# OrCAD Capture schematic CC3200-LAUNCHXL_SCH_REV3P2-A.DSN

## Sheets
1 5. Sensors. Power: size A2; title: CC3101 LP Ver 2.0; rev: A; company: Texas Instruments; note: 66/3 Bagmane Tech Park; note: CV Raman Nagar
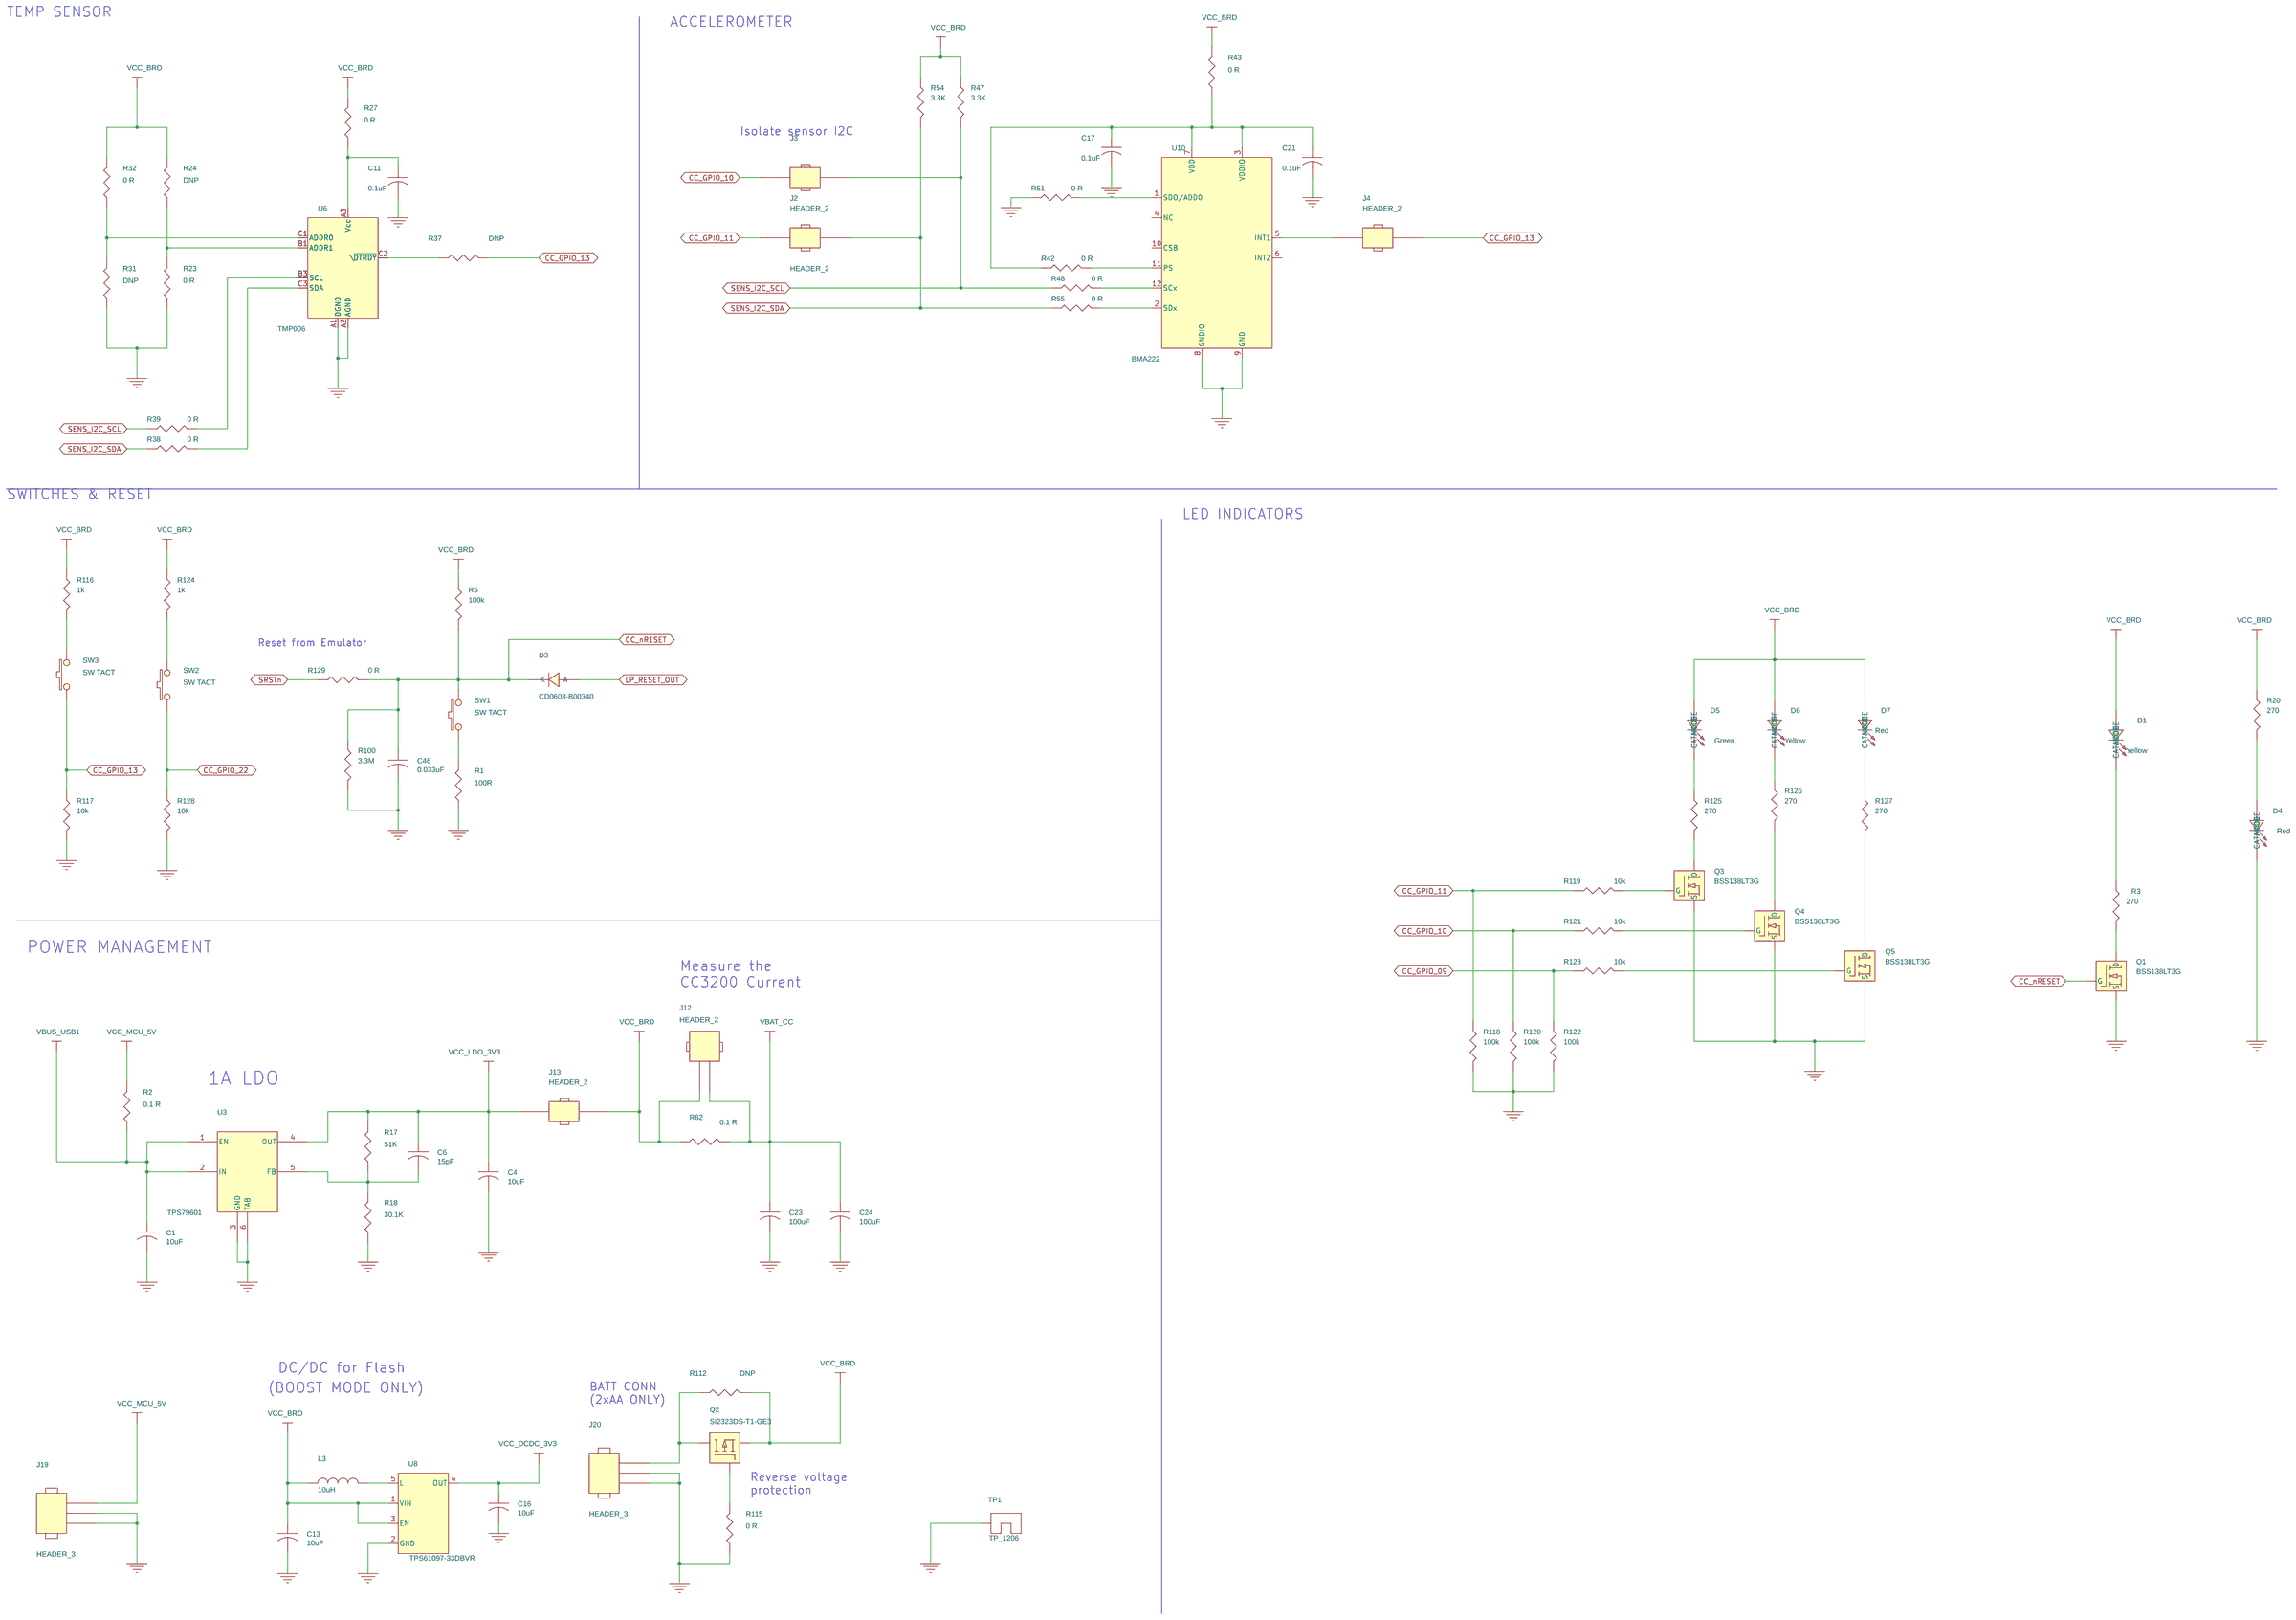
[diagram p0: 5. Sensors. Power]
2 4. ICDI: size A2; title: CC3101 LP Ver 3.0
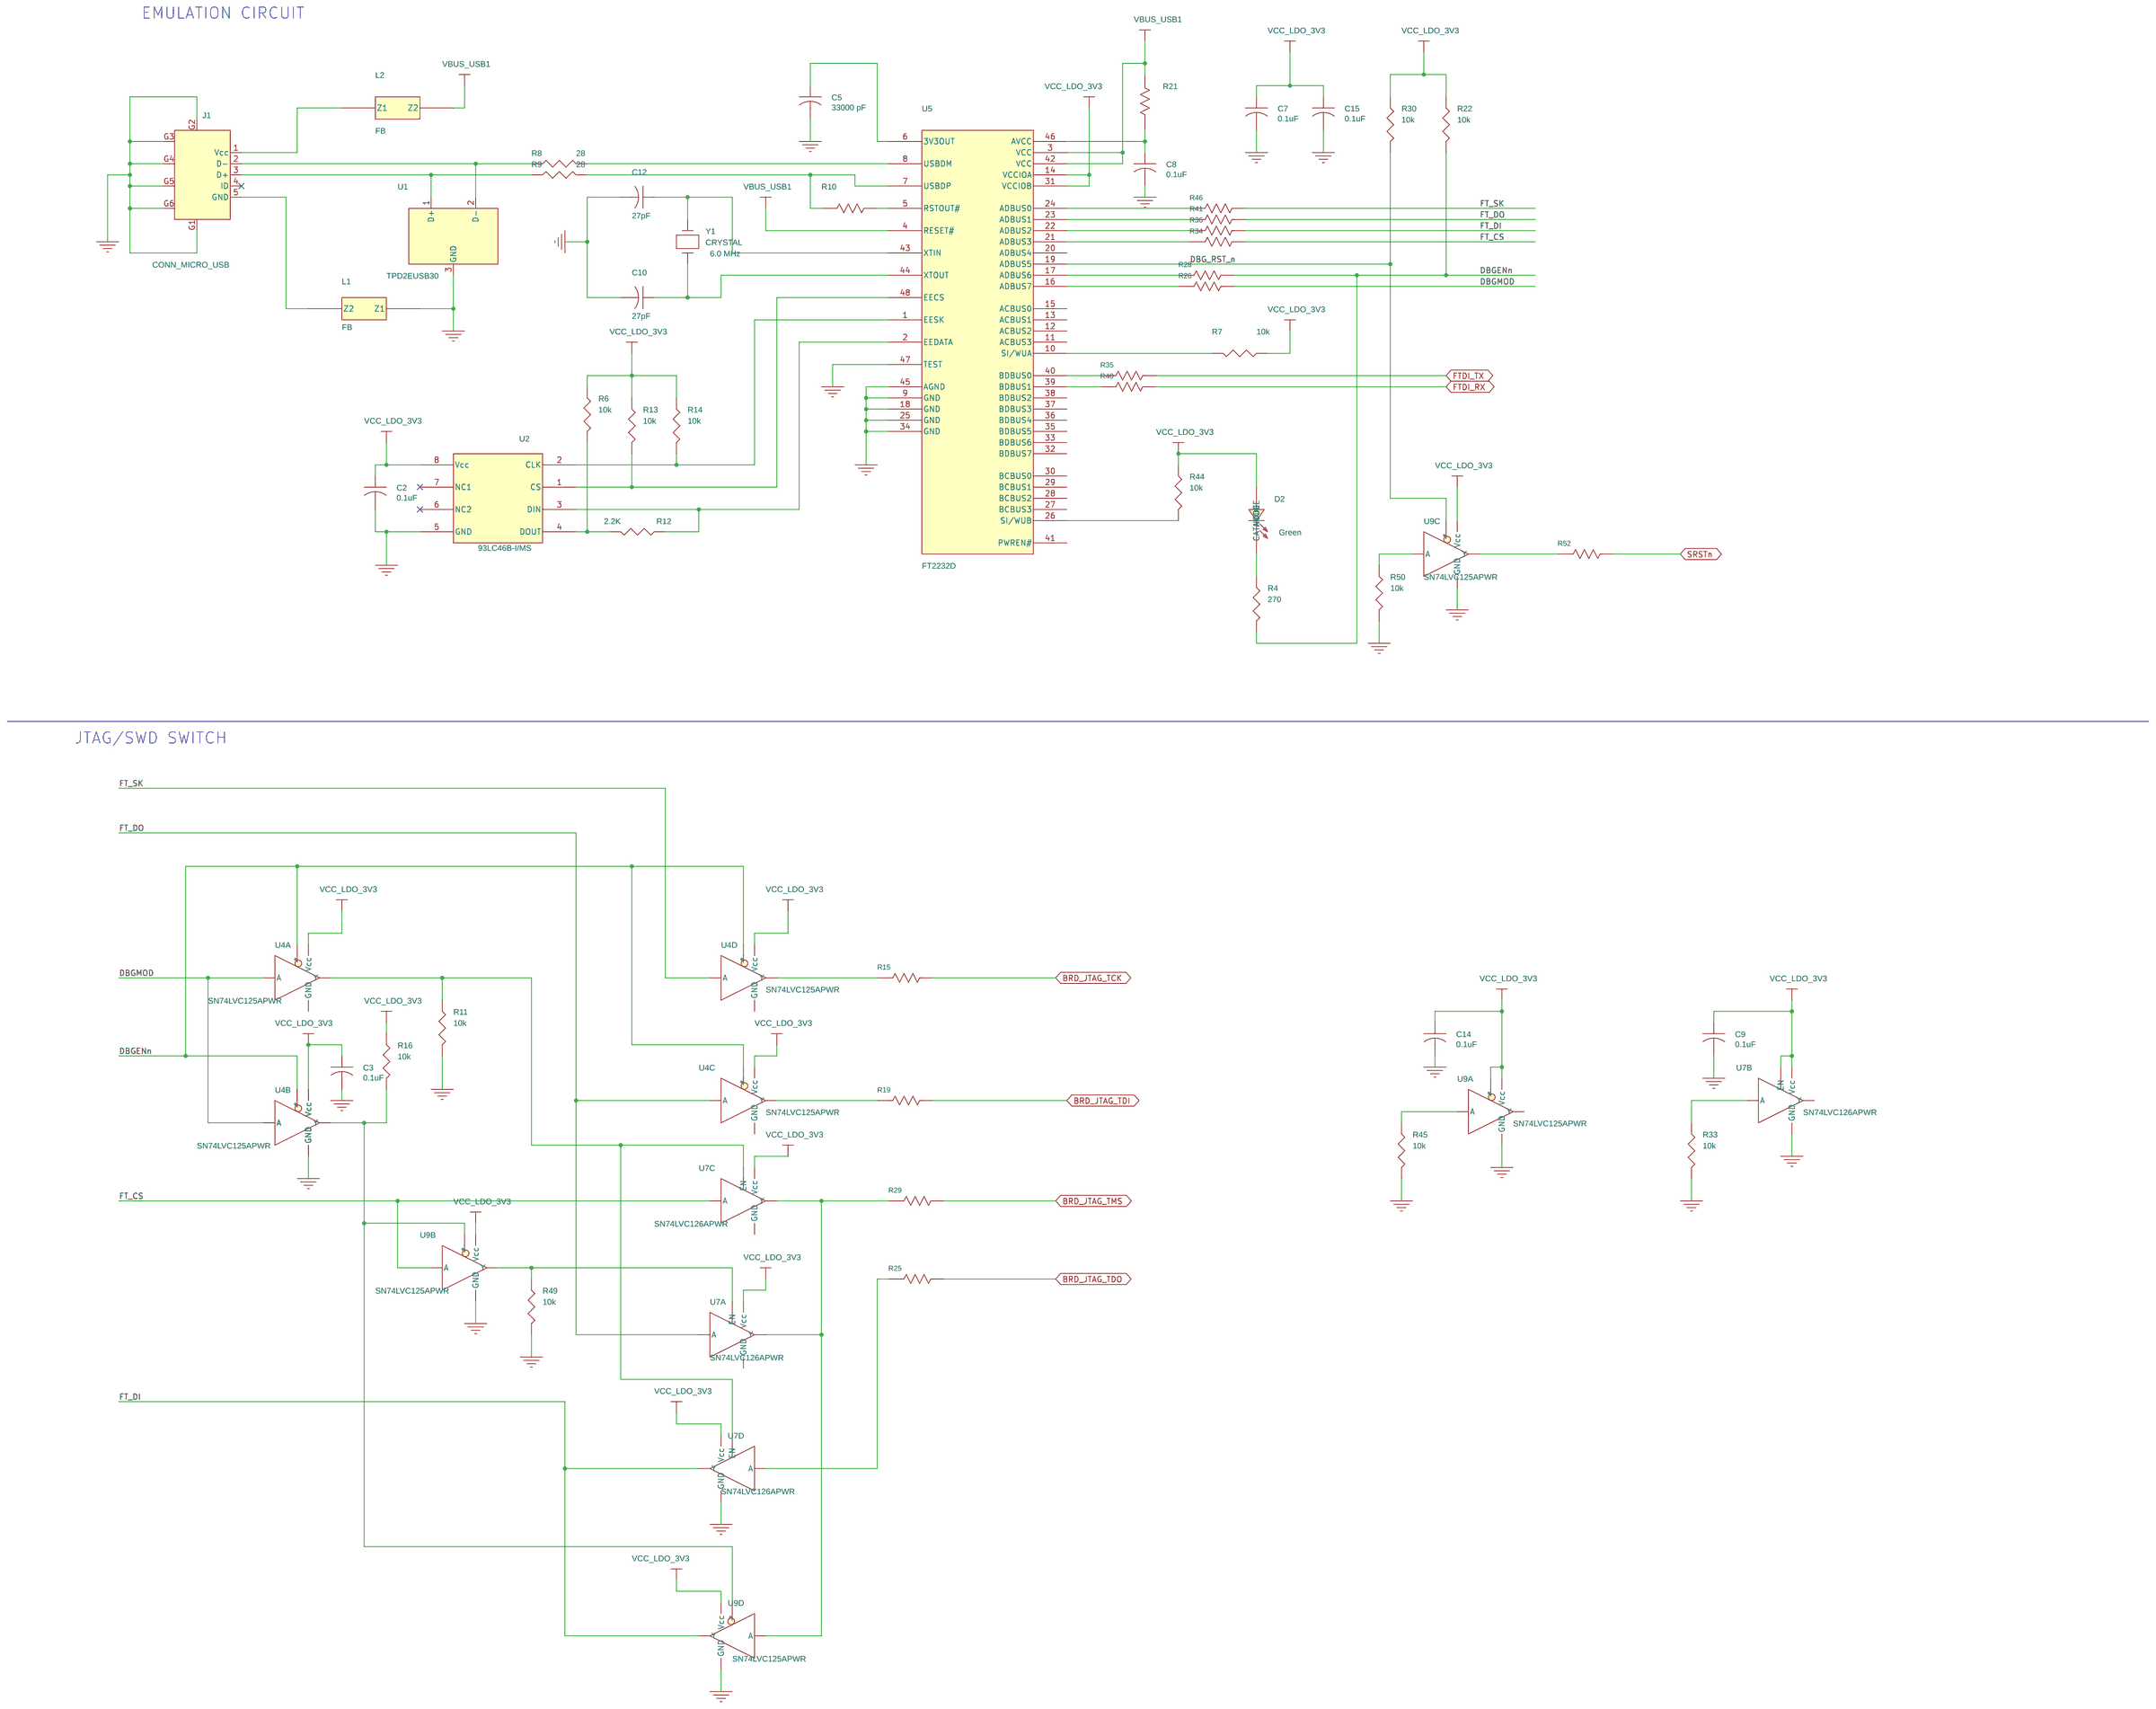
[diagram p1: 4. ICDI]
3 3. HOST INTERFACE: size A2
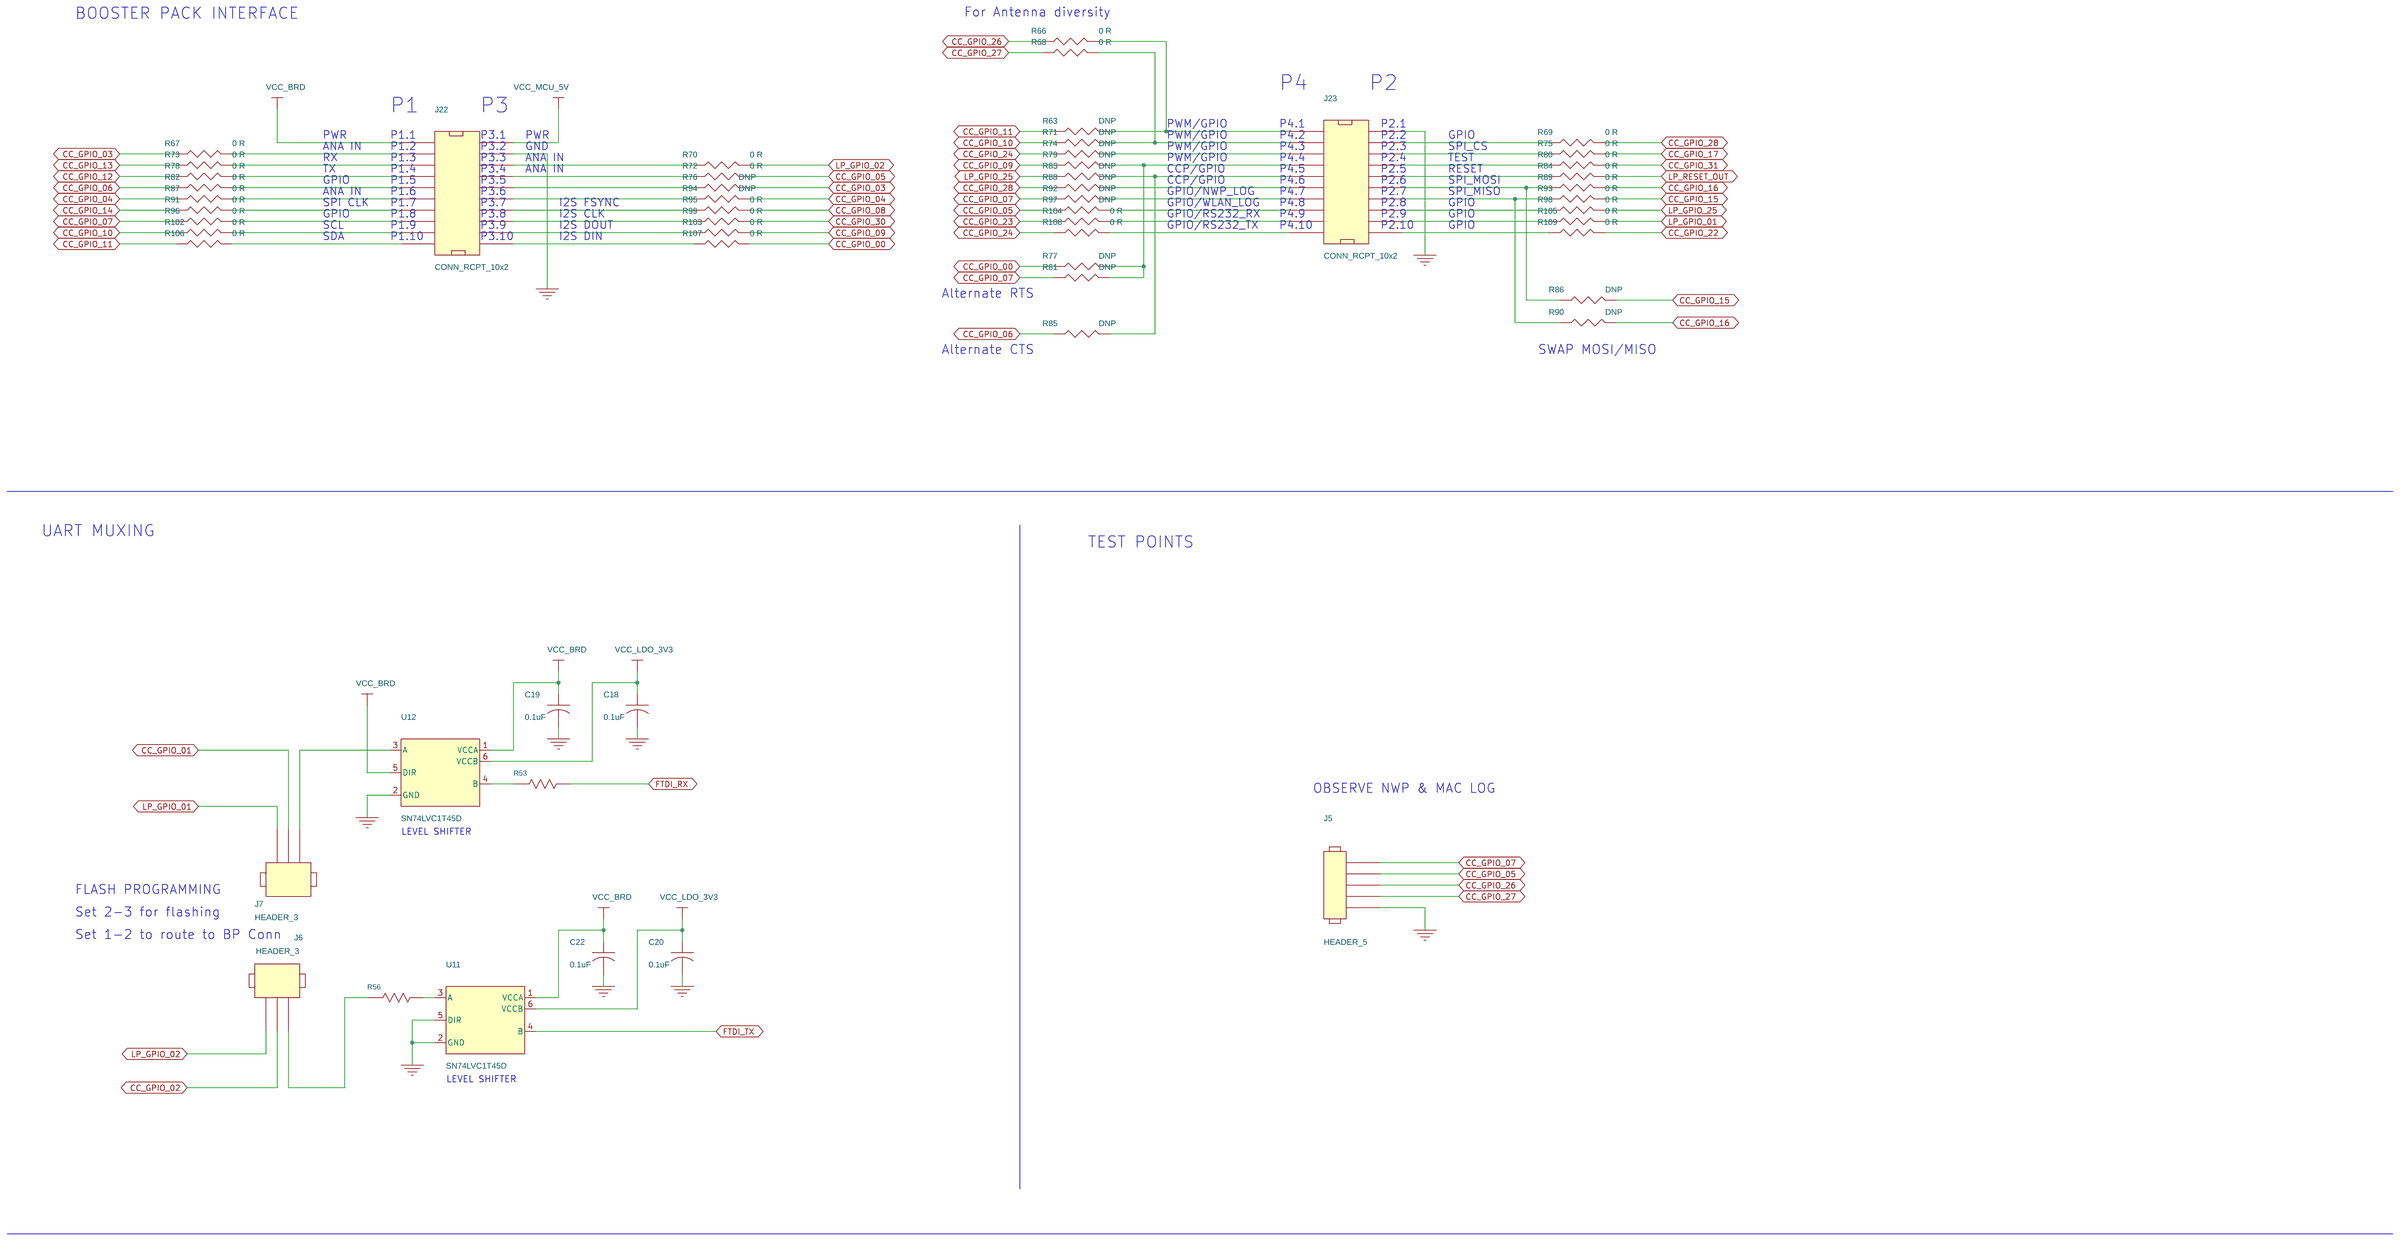
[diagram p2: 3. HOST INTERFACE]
4 2. Main Page: size A2; title: CC3101 LP Ver 3.0; rev: B
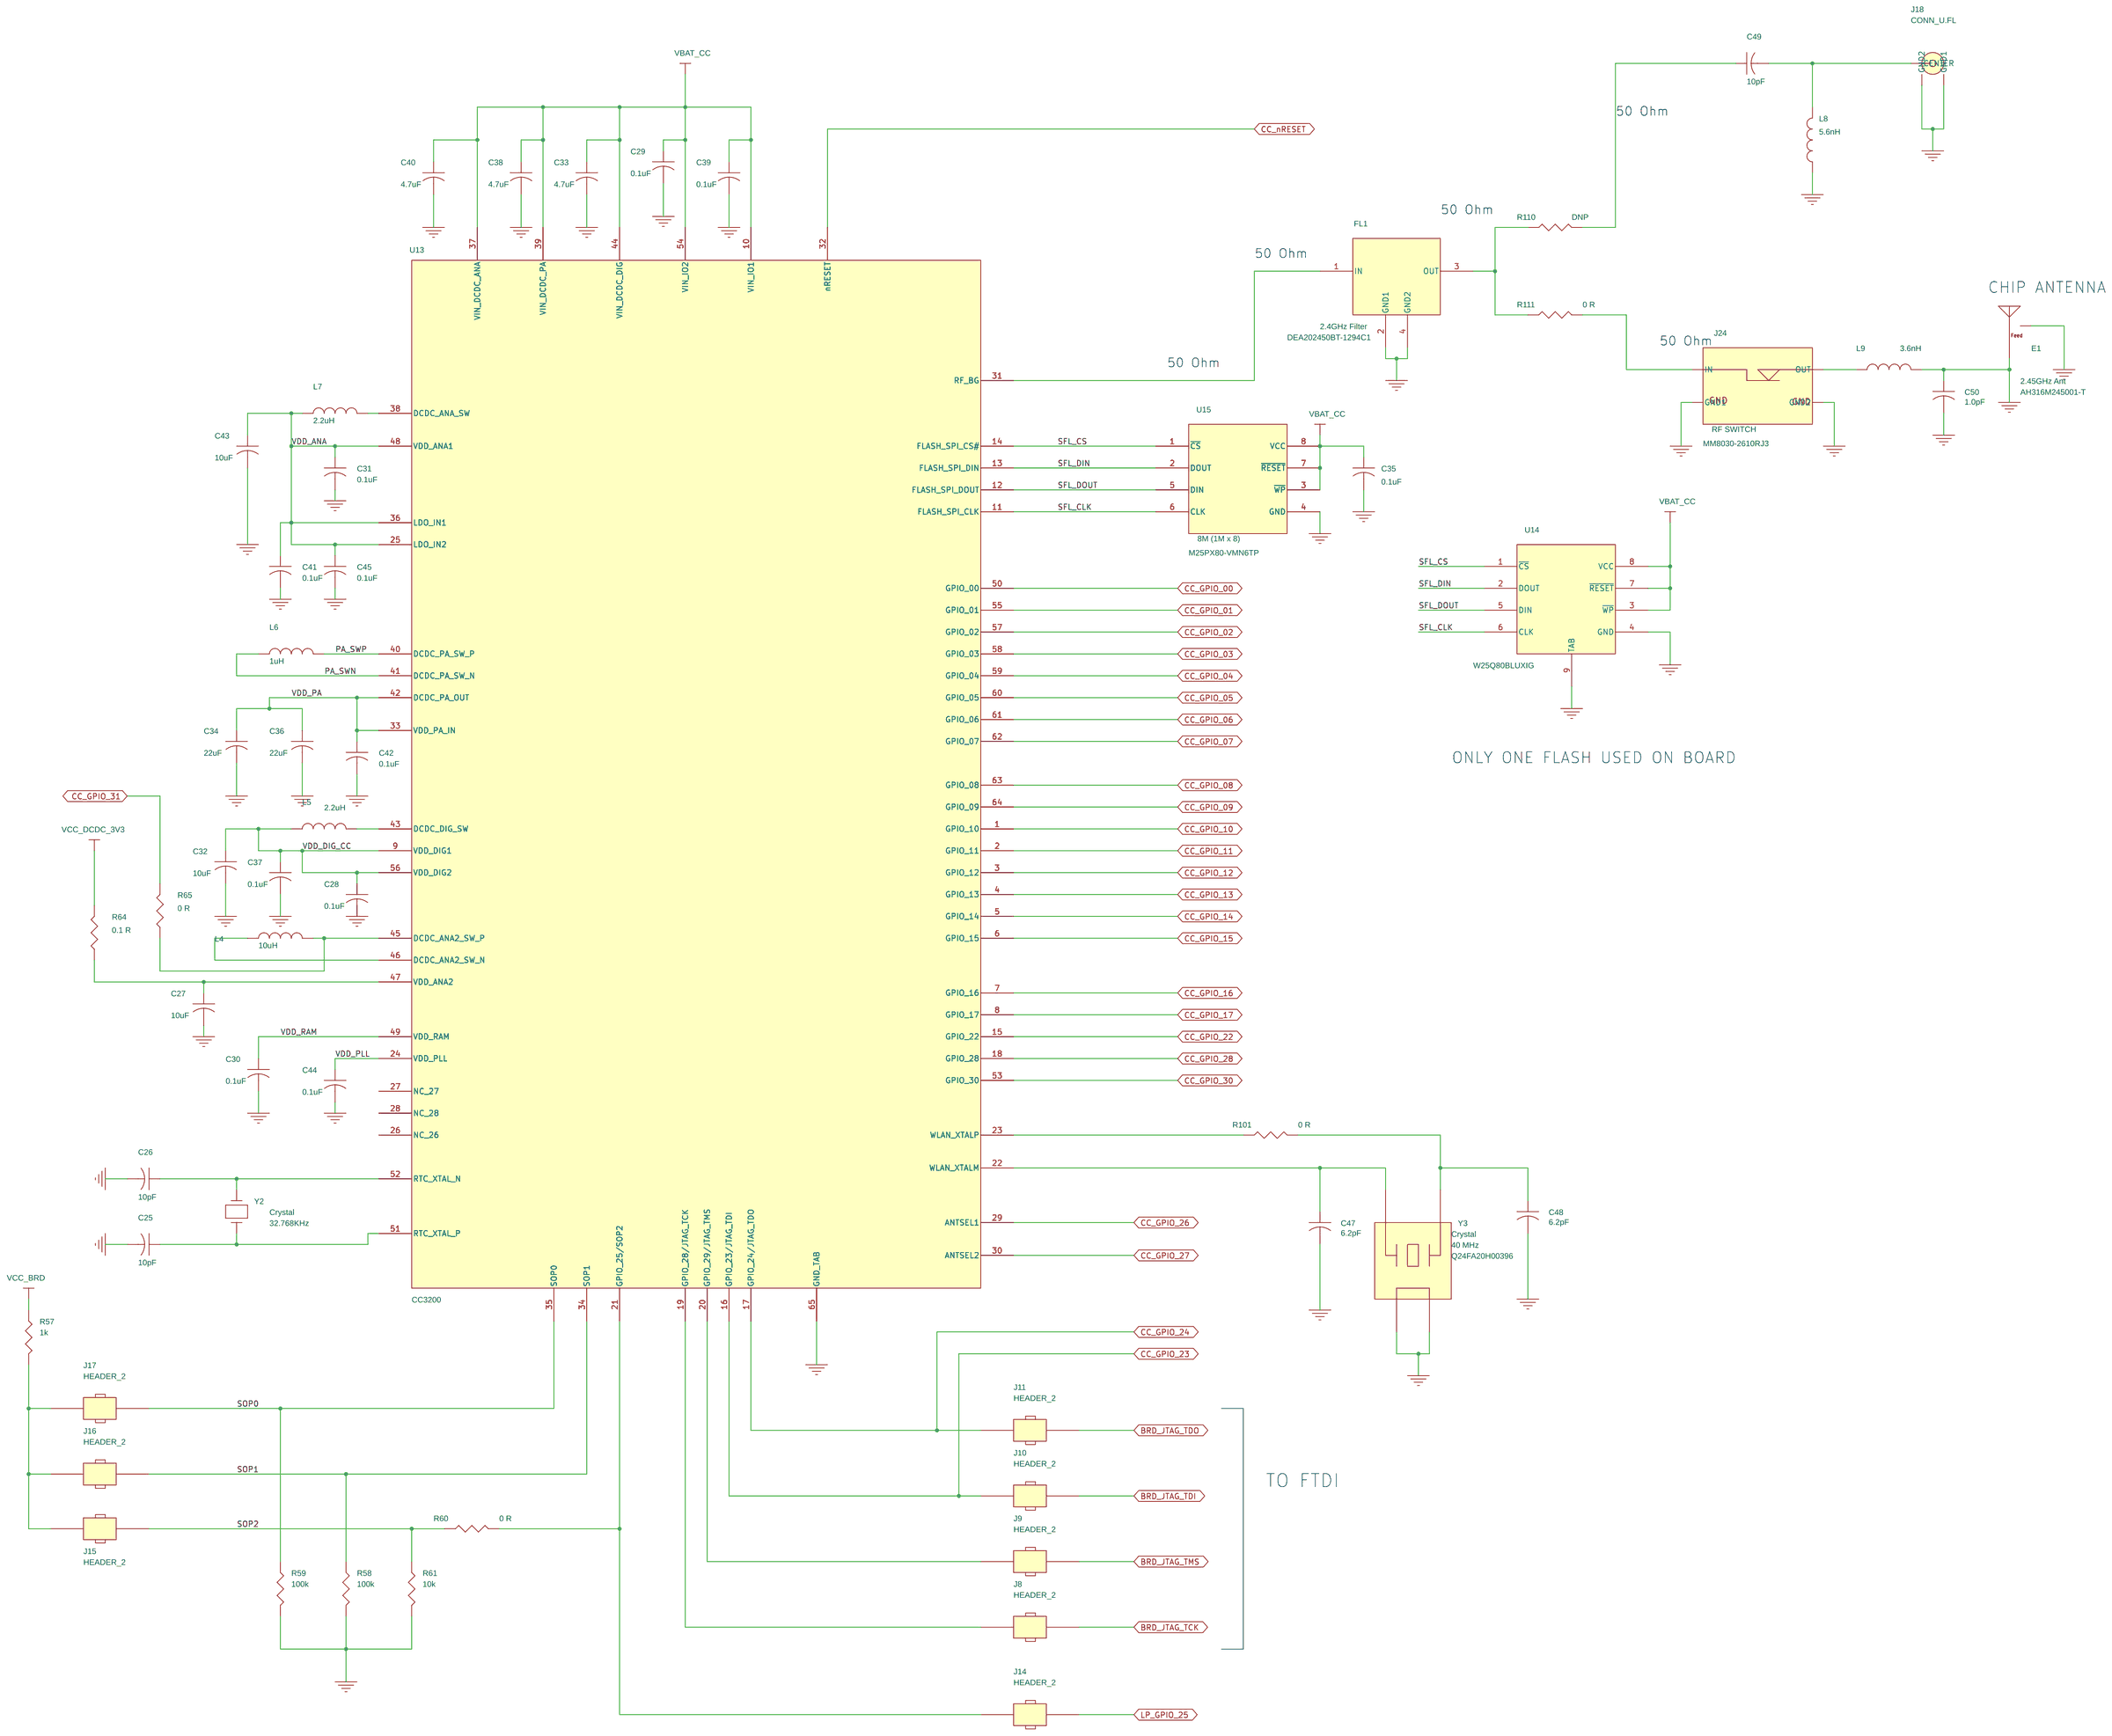
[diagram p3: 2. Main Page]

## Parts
sheet 2. Main Page
C25  10pF  [CC0402]
C26  10pF  [CC0402]
C27  10uF  [CC0603]
C28  0.1uF  [CC0402]
C29  0.1uF  [CC0402]
C30  0.1uF  [CC0402]
C31  0.1uF  [CC0402]
C32  10uF  [CC0603]
C33  4.7uF  [CC0402]
C34  22uF  [CC0603]
C35  0.1uF  [CC0402]
C36  22uF  [CC0603]
C37  0.1uF  [CC0402]
C38  4.7uF  [CC0402]
C39  0.1uF  [CC0402]
C40  4.7uF  [CC0402]
C41  0.1uF  [CC0402]
C42  0.1uF  [CC0402]
C43  10uF  [CC0603]
C44  0.1uF  [CC0402]
C45  0.1uF  [CC0402]
C47  6.2pF  [CC0402]
C48  6.2pF  [CC0402]
C49  10pF  [CC0402]
C50  1.0pF  [indc_0402cs]
E1  2.45GHz Ant  [ANT_AH316M]
FL1  2.4GHz Filter  [FIL_DEA202450BT-1294C1]
J8  HEADER_2  [HDR_THVT_1x2_100_M]
J9  HEADER_2  [HDR_THVT_1x2_100_M]
J10  HEADER_2  [HDR_THVT_1x2_100_M]
J11  HEADER_2  [HDR_THVT_1x2_100_M]
J14  HEADER_2  [HDR_THVT_1x2_100_M]
J15  HEADER_2  [HDR_THVT_1x2_100_M]
J16  HEADER_2  [HDR_THVT_1x2_100_M]
J17  HEADER_2  [HDR_THVT_1x2_100_M]
J18  CONN_U.FL  [EMERSON_128-0711-201_NEW]
J24  RF SWITCH  [CON_RF_MM8030-2600B]
L4  10uH  [0805]
L5  2.2uH  [INDC2520X100N_MM]
L6  1uH  [IND_CB2518_MM]
L7  2.2uH  [INDC2520X100N_MM]
L8  5.6nH  [indc_0402cs]
L9  3.6nH  [CC0402]
R57  1k  [rc0402]
R58  100k  [rc0402]
R59  100k  [rc0402]
R60  0 R  [rc0402]
R61  10k  [rc0402]
R64  0.1 R  [rc0805]
R65  0 R  [rc0402]
R101  0 R  [rc0402]
R110  DNP  [RC0402]
R111  0 R  [rc0402]
U13  CC3200  [QFN50P900X900_64_PWP_A_EINF]
U14  8M (1M x 8)  [PSON50P300X200X60-9N]
U15  8M (1M x 8)  [SOIC_8_197x157_50]
Y2  Crystal  [xtal_abs07]
Y3  Crystal  [XTAL_4_SM_104x83x20]
sheet 3. HOST INTERFACE
C18  0.1uF  [CC0402]
C19  0.1uF  [CC0402]
C20  0.1uF  [CC0402]
C22  0.1uF  [CC0402]
J5  HEADER_5  [HDR_THVT_1x5_100_M]
J6  HEADER_3  [HDR_THVT_1x3_100_M]
J7  HEADER_3  [HDR_THVT_1x3_100_M]
J22  CONN_RCPT_10x2  [HDR_THVT_2X10_100_F]
J23  CONN_RCPT_10x2  [HDR_THVT_2X10_100_F]
R53  33  [RC0402]
R56  33  [RC0402]
R63  DNP  [RC0402]
R66  0 R  [rc0402]
R67  0 R  [rc0402]
R68  0 R  [rc0402]
R69  0 R  [rc0402]
R70  0 R  [rc0402]
R71  DNP  [RC0402]
R72  0 R  [rc0402]
R73  0 R  [rc0402]
R74  DNP  [RC0402]
R75  0 R  [rc0402]
R76  DNP  [RC0402]
R77  DNP  [RC0402]
R78  0 R  [rc0402]
R79  DNP  [RC0402]
R80  0 R  [rc0402]
R81  DNP  [RC0402]
R82  0 R  [rc0402]
R83  DNP  [RC0402]
R84  0 R  [rc0402]
R85  DNP  [RC0402]
R86  DNP  [RC0402]
R87  0 R  [rc0402]
R88  DNP  [RC0402]
R89  0 R  [rc0402]
R90  DNP  [RC0402]
R91  0 R  [rc0402]
R92  DNP  [RC0402]
R93  0 R  [rc0402]
R94  DNP  [RC0402]
R95  0 R  [rc0402]
R96  0 R  [rc0402]
R97  DNP  [RC0402]
R98  0 R  [rc0402]
R99  0 R  [rc0402]
R102  0 R  [rc0402]
R103  0 R  [rc0402]
R104  0 R  [rc0402]
R105  0 R  [rc0402]
R106  0 R  [rc0402]
R107  0 R  [rc0402]
R108  0 R  [rc0402]
R109  0 R  [rc0402]
U11  SN74LVC1T45D  [sot65p210x110-6n]
U12  SN74LVC1T45D  [sot65p210x110-6n]
sheet 4. ICDI
C2  0.1uF  [CC0402]
C3  0.1uF  [CC0402]
C5  33000 pF  [cc0402]
C7  0.1uF  [CC0402]
C8  0.1uF  [CC0402]
C9  0.1uF  [CC0402]
C10  27pF  [CC0402]
C12  27pF  [CC0402]
C14  0.1uF  [CC0402]
C15  0.1uF  [CC0402]
D2  LED  [LED_0603]
J1  CONN_MICRO_USB  [FCI_10118194-0001]
L1  FB  [INDC0603]
L2  FB  [INDC0603]
R4  270  [RC0603]
R6  10k  [rc0402]
R7  10k  [rc0402]
R8  28  [RC0402]
R9  28  [RC0402]
R10  1.5k  [RC0402]
R11  10k  [rc0402]
R12  2.2K  [rc0402]
R13  10k  [rc0402]
R14  10k  [rc0402]
R15  33  [RC0402]
R16  10k  [rc0402]
R19  33  [RC0402]
R21  470  [RC0402]
R22  10k  [rc0402]
R25  33  [RC0402]
R26  33  [RC0402]
R28  33  [RC0402]
R29  33  [RC0402]
R30  10k  [rc0402]
R33  10k  [rc0402]
R34  33  [RC0402]
R35  33  [RC0402]
R36  33  [RC0402]
R40  33  [RC0402]
R41  33  [RC0402]
R44  10k  [rc0402]
R45  10k  [rc0402]
R46  33  [RC0402]
R49  10k  [rc0402]
R50  10k  [rc0402]
R52  33  [RC0402]
U1  TPD2EUSB30  [SOT35P100X50-3N]
U2  93LC46B-I/MS  [TI_MSOP8_0P65_3]
U4  SN74LVC125APWR  [TSSOP_14_201x177_26]  (sections A,B,C,D)
U5  FT2232D  [QFP_48_284X284_20]
U7  SN74LVC126APWR  [TSSOP_14_201x177_26]  (sections A,B,C,D)
U9  SN74LVC125APWR  [TSSOP_14_201x177_26]  (sections A,B,C,D)
Y1  CRYSTAL  [xtal_2p_th_1p1mmp]
sheet 5. Sensors. Power
C1  10uF  [CC0805]
C4  10uF  [CC0805]
C6  15pF  [CC0402]
C11  0.1uF  [CC0402]
C13  10uF  [CC0603]
C16  10uF  [CC0603]
C17  0.1uF  [CC0402]
C21  0.1uF  [CC0402]
C23  100uF  [TANT_1206]
C24  100uF  [TANT_1206]
C46  0.033uF  [CC0402]
D1  LED  [LED_0603]
D3  CD0603-B00340  [DIO_CD0603-S0180R_CUS]
D4  LED  [LED_0603]
D5  LED  [LED_0603]
D6  LED  [LED_0603]
D7  LED  [LED_0603]
J2  HEADER_2  [HDR_THVT_1x2_100_M]
J3  HEADER_2  [HDR_THVT_1x2_100_M]
J4  HEADER_2  [HDR_THVT_1x2_100_M]
J12  HEADER_2  [HDR_THVT_1x2_100_M]
J13  HEADER_2  [HDR_THVT_1x2_100_M]
J19  HEADER_3  [HDR_THVT_1x3_100_M]
J20  HEADER_3  [HDR_THVT_1x3_100_M]
L3  10uH  [IND_CB2518_MM]
Q1  BSS138LT3G  [SOT_23_321]
Q2  SI2323DS-T1-GE3  [SOT_23_321]
Q3  BSS138LT3G  [SOT_23_321]
Q4  BSS138LT3G  [SOT_23_321]
Q5  BSS138LT3G  [SOT_23_321]
R1  100R  [rc0402]
R2  0.1 R  [rc0805]
R3  270  [RC0603]
R5  100k  [rc0402]
R17  51K  [rc0402]
R18  30.1K  [rc0402]
R20  270  [RC0603]
R23  0 R  [rc0402]
R24  DNP  [RC0402]
R27  0 R  [rc0402]
R31  DNP  [RC0402]
R32  0 R  [rc0402]
R37  DNP  [RC0603]
R38  0 R  [rc0402]
R39  0 R  [rc0402]
R42  0 R  [rc0402]
R43  0 R  [rc0402]
R47  3.3K  [rc0402]
R48  0 R  [rc0402]
R51  0 R  [rc0402]
R54  3.3K  [rc0402]
R55  0 R  [rc0402]
R62  0.1 R  [rc0805]
R100  3.3M  [RC0402]
R112  DNP  [RC0603]
R115  0 R  [rc0402]
R116  1k  [rc0402]
R117  10k  [rc0402]
R118  100k  [rc0402]
R119  10k  [rc0402]
R120  100k  [rc0402]
R121  10k  [rc0402]
R122  100k  [rc0402]
R123  10k  [rc0402]
R124  1k  [rc0402]
R125  270  [RC0603]
R126  270  [RC0603]
R127  270  [RC0603]
R128  10k  [rc0402]
R129  0 R  [rc0402]
SW1  SW TACT  [SW_EVQ-11A05R]
SW2  SW TACT  [SW_EVQ-11A05R]
SW3  SW TACT  [SW_EVQ-11A05R]
TP1  TP_1206  [TP_RCW1206]
U3  TPS79601  [SOT_223_6_TG]
U6  TMP006  [bga8c50p3x3_153x153x63]
U8  TPS61097-33DBVR  [SOT_23_5]
U10  BMA222  [LGA12R50P4X4_200X200X100]

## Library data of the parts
C25 C26 = CAP: CAP CER 10PF 50V 1% NP0 0402; Distributor_Part_Number: 490-6186-1-ND; Mfr_Name: Murata Electronics North America; Mfr_Part_Number: GRM1555C1H100FA01D; TI_Part_No: TI-CAP-GRM1555C1H100FA01D; Tolerance: ±1%; Voltage_Rating: 50V; Datasheet: http://media.digikey.com/pdf/Data%20Sheets/Murata%20PDFs/GRM%20Series%20Data.pdf
C27 C32 C43 = C: CAP CER 10UF 6.3V 20% X5R 0603; Distributor: Digi-Key; Distributor PN: 490-3896-1-ND; Distributor_Name: Digi-Key; Distributor_Part_Number: 490-3896-2-ND; Manufacturer: Murata Electronics North America; Manufacturer PN: GRM188R60J106ME47D; Mfr_Name: Murata Electronics North America; Mfr_Part_Number: GRM188R60J106ME47D; TI_Part_No: TI-RES-GRM188R60J106ME47D; Tolerance: 20%; Voltage_Rating: 6.3V
C11 C17-C22 C28-C31 C35 C37 C39 C41 C42 C44 C45 = C: CAP CER 0.1UF 10V 10% X5R 0402; Distributor: Digi-Key; Distributor PN: 587-1227-1-ND; Distributor_Name: Digi-Key; Distributor_Part_Number: 587-1227-1-ND; Manufacturer: Taiyo Yuden; Manufacturer PN: LMK105BJ104KV-F; Mfr_Name: Taiyo Yuden; Mfr_Part_Number: LMK105BJ104KV-F; TI_Part_No: TI-CAP-LMK105BJ104KV-F; Tolerance: +/-10%; Datasheet: 587-1227-1-ND
C33 C38 C40 = C: CAP CER 4.7UF 6.3V 20% X5R 0402; Distributor: Digi-Key; Distributor PN: 1276-1056-1-ND; Distributor_Part_Number: 1276-1056-2-ND; Manufacturer: Samsung Electro-Mechanics America, Inc; Manufacturer PN: CL05A475MQ5NRNC; Mfr_Name: Samsung Electro-Mechanics America, Inc; Mfr_Part_Number: CL05A475MQ5NRNC; TI_Part_No: TI-CAP-CL05A475MQ5NRNC
C34 C36 = C: CAP CER 22UF 4V 20% X5R 0603; Distributor: Digi-Key; Distributor PN: 587-3262-2-ND; Distributor_Part_Number: 587-3262-1-ND; Manufacturer: Taiyo Yuden; Manufacturer PN: AMK107BBJ226MAHT; Mfr_Name: Taiyo Yuden; Mfr_Part_Number: AMK107BBJ226MAHT; TI_Part_No: TI-CAP-AMK107BBJ226MAHT; Tolerance: 20%; Voltage_Rating: 4V
C47 C48 = CAP: CAP CER 6.2PF 50V NP0 0402; Distributor_Part_Number: 490-8224-1-ND; Mfr_Name: Murata Electronics North America; Mfr_Part_Number: GRM1555C1H6R2BA01D; Tolerance: ±0.1pF; Voltage_Rating: 50V; Datasheet: http://media.digikey.com/pdf/Data%20Sheets/Murata%20PDFs/GRM%20Series%20Data.pdf
C49 = CAP: CAP CER 10PF 50V NP0 0402; Distributor_Part_Number: 478-5991-2-ND; Mfr_Name: AVX Corporation; Mfr_Part_Number: 04025U100CAT2A; TI_Part_No: TI-CAP-04025U100CAT2A
C50 = CAP: CAP CER 1PF 50V NP0 0402; Distributor_Part_Number: 490-6073-1-ND; Mfr_Name: Murata Electronics North America; Mfr_Part_Number: GJM1555C1H1R0BB01D; Tolerance: ±0.1pF; Voltage_Rating: 50V; Datasheet: http://www.murata.com/products/catalog/pdf/c02e.pdf
E1 = CHIP_ANTENNA_2T: ANT BLUETOOTH W-LAN ZIGBEE WIMAX; Distributor: Digi-Key; Distributor PN: 587-2200-1-ND; Distributor_Part_Number: 587-2200-1-ND; Manufacturer: Taiyo Yuden; Manufacturer PN: AH316M245001-T; Mfr_Name: Taiyo Yuden; Mfr_Part_Number: AH316M245001-T
FL1 = TDK_FILTER_DEA20: FILTER BANDPASS 2.45GHZ WLAN SMD; Distributor_Part_Number: DEA202450BT-1294C1; Mfr_Name: TDK-Epcos; Mfr_Part_Number: DEA202450BT-1294C1; TI_Part_No: TI-FIL-DEA202450BT-1294C1
J2-J4 J8-J11 J13-J17 = HEADER_1X2: CONN HEADR BRKWAY .100 2POS STR; Distributor_Part_Number: 5-146285-2-ND; Mfr_Name: TE Connectivity; Mfr_Part_Number: 5-146285-2; TI_Part_No: TI-CON-5-146285-2; Datasheet: http://www.te.com/commerce/DocumentDelivery/DDEController?Action=srchrtrv&DocNm=146285&DocType=Customer+Drawing&DocLang=English
J18 = CONN_UFL_3P: CONN UMC RCPT STR 50 OHM SMD; Distributor_Part_Number: J983CT-ND; FPLIST: EMERSON_128-0711-201, EMERSON_128-0711-201_NEW; Mfr_Name: Emerson Network Power Connectivity Johnson; Mfr_Part_Number: 128-0711-201; TI_Part_No: TI-COAX-128-0711-201
J24 = CONN_COAX_MURATA_4P: CONN SWG JACK STR 50 OHM SMD; Distributor_Part_Number: 490-4981-2-ND; Mfr_Name: Murata; Mfr_Part_Number: MM8030-2610RJ3; TI_Part_No: TI-CON-MM8030-2610J13; Datasheet: http://www.murata.com/products/catalog/pdf/o33e.pdf
L4 = INDUCTOR: INDUCTOR POWER 10UH 0805; Current_Rating: 350mA; DC_Resistance: 470mOhm; Distributor_Part_Number: 445-6396-1-ND; FPLIST: 0805,INDC0805; Mfr_Name: TDK; Mfr_Part_Number: MLZ2012M100W; TI_Part_No: TI-IND-MLZ2012M100W; Tolerance: 20%
L5 L7 = INDUCTOR: INDUCTOR 2.2UH 20% 1300MA 1008; Current Rating: 1.3A; Current_Rating: 1.3A; DC Resistance: 100 mOhm Max; Distributor: Digi-Key; Distributor PN: 490-5114-1-ND; Distributor_Part_Number: 490-5114-1-ND; Manufacturer: Murata Electronics North America; Manufacturer PN: LQM2HPN2R2MG0L; Mfr_Name: Murata Electronics North America; Mfr_Part_Number: LQM2HPN2R2MG0L; TI_Part_No: TI-IND-LQM2HPN2R2MG0L
L6 = INDUCTOR: INDUCTOR POWER 1.0UH 1007; Current_Rating: 1.5A; DC_Resistance: 90mOhm; Distributor_Part_Number: 490-6699-1-ND; Mfr_Name: Murata; Mfr_Part_Number: LQM2HPN1R0MJ0L; TI_Part_No: TI-IND-LQM2HPN1R0MJ0L; Tolerance: 20%
L8 = INDUCTOR: INDUCTOR HIFREQ 5.6+/-0.3NH 0402; Distributor_Name: Digi-Key; Distributor_Part_Number: 587-1513-1-ND; Manufacturer: Taiyo Yuden; Manufacturer PN: HK10055N6S-T; Mfr_Name: Taiyo Yuden; Mfr_Part_Number: HK10055N6S-T; TI_Part_No: TI-IND-HK10055N6S-T
L9 = INDUCTOR: INDUCTOR 3.6NH 0.1NH 0402; DC_Resistance: 500 mOhm Max; Distributor_Part_Number: 490-6756-1-ND; Mfr_Name: Murata Electronics North America; Mfr_Part_Number: LQP15MN3N6B02D; Tolerance: ±0.1nH; Datasheet: http://search.murata.co.jp/Ceramy/image/img/PDF/ENG/L0075S0084LQP15M.pdf
R57 = RESISTOR_v2: RES 1.0K OHM 1/16W 5% 0402 SMD; Distributor: Digi-Key; Distributor PN: 311-1.0KJRTR-ND; Distributor_Part_Number: 311-1.0KJRCT-ND; Manufacturer: Yageo; Manufacturer PN: RC0402JR-071KL; Mfr_Name: Yageo; Mfr_Part_Number: RC0402JR-071KL; Tolerance: 5%
R58 R59 = RESISTOR_v2: RES 100K OHM 1/16W 5% 0402 SMD; Distributor: Digi-Key; Distributor PN: 311-100KJRTR-ND; Distributor_Part_Number: 311-100KJRCT-ND; Manufacturer: Yageo; Manufacturer PN: RC0402JR-07100KL; Mfr_Name: Yageo; Mfr_Part_Number: RC0402JR-07100KL; Tolerance: 5%
R60 R65-R70 R72 R73 R75 R78 R80 R82 R84 R87 R89 R91 R93 R95 R96 R98 R99 R101-R109 R111 R129 = RESISTOR_v2: RES 0.0 OHM 1/10W JUMP 0402 SMD; Distributor: Digi-Key; Distributor PN: P0.0JTR-ND; Distributor_Name: Digi-Key; Distributor_Part_Number: P0.0JTR-ND; Manufacturer: Panasonic Electronic Components; Manufacturer PN: ERJ-2GE0R00X; Mfr_Name: Panasonic Electronic Components; Mfr_Part_Number: ERJ-2GE0R00X; TI_Part_No: TI-Panasonic-ERJ-2GE0R00X
R61 = RESISTOR_v2: RES 10K OHM 1/16W 5% 0402 SMD; Distributor: Digi-Key; Distributor PN: 311-10KJRTR-ND; Distributor_Name: Digi-Key; Distributor_Part_Number: 311-10KJRCT-ND; Manufacturer: Yageo; Manufacturer PN: RC0402JR-0710KL; Mfr_Name: Yageo; Mfr_Part_Number: RC0402JR-0710KL; TI_Part_No: TI-RES-RC0402JR-0710KL; Tolerance: 5%
R2 R62 R64 = RESISTOR_v2: RES 0.1 OHM 1/4W 1% 0805 SMD; Distributor: Digi-Key; Distributor_Name: Digi-Key; Distributor_Part_Number: P.1BJCT-ND; Manufacturer: Panasonic Electronic Components; Manufacturer PN: ERJ-S6SFR10V; Mfr_Name: Panasonic; Mfr_Part_Number: ERJ-S6SFR10V; TI_Part_No: TI-RES-ERJ-S6SFR10V; Tolerance: 1%
R24 R31 R63 R71 R74 R76 R77 R79 R81 R83 R85 R86 R88 R90 R92 R94 R97 R110 = RESISTOR_v2: DO NOT MOUNT; Distributor_Part_Number: TI-RES-DNP-0402; Tolerance: NA
U13 = CC3101_LP_V2_0: ARM M4 MCU with 802.11bg WIFI; Distributor_Part_Number: TI-IC-CC3101ZRTDR; Mfr_Name: Texas Instruments; Mfr_Part_Number: XCC3200HZ; TI_Part_No: TI-IC-CC3101ZRTDR; Datasheet: Custom
U14 = FLASH_USON: IC FLASH 8MBIT 75MHZ 8WSON; Distributor_Part_Number: TI-IC-W25Q80BLUXIG; Mfr_Name: Winbond; Mfr_Part_Number: W25Q80BLUXIG; TI_Part_No: TI-IC-W25Q80BLUXIG; Datasheet: Z:\Database\TI_Database\Datasheets\W25Q80BL.pdf
U15 = FLASH: IC FLASH 8MBIT 75MHZ 8SO; Distributor_Name: Digi-Key; Distributor_Part_Number: M25PX80-VMN6TPTR-ND; Mfr_Name: Micron Technology Inc; Mfr_Part_Number: M25PX80-VMN6TP; TI_Part_No: TI-IC-M25PX80-VMN6TP
Y2 = CRYSTAL: CRYSTAL 32.768KHZ 12.5PF SMD; Distributor_Part_Number: 535-9542-1-ND; Frequency: 32.768KHz; Mfr_Name: Abracon Corporation; Mfr_Part_Number: ABS07-32.768KHZ-T; TI_Part_No: TI-Crystal-ABS07-32.768KHZ-T
Y3 = CRYSTAL_EPSON_FA20H_4P: CRYSTAL 40MHZ 8PF SMD; Distributor_Part_Number: Q24FA20H00396; Frequency: 40 MHz; Mfr_Name: Epson; Mfr_Part_Number: Q24FA20H00396; TI_Part_No: TI-Crystal-Q24FA20H00396
J5 = HEADER_5: CONN HEADER VERT 5 POS .100 TIN; Distributor_Part_Number: 22-28-4051-ND; Mfr_Name: Molex/GC/Waldom Inc.; Mfr_Part_Number: 22-28-4051; TI_Part_No: TI-CON-22-28-4051; Datasheet: http://www.digikey.com/orcad.DKS$P=22-28-4051-ND
J6 J7 J19 J20 = HEADER_3: CONN HDR BRKWAY .100 3POS VERT; Distributor_Part_Number: A106719-ND; Mfr_Name: TE Connectivity; Mfr_Part_Number: 5-146282-3; TI_Part_No: TI-CON-5-146282-3; Datasheet: http://www.te.com/commerce/DocumentDelivery/DDEController?Action=srchrtrv&DocNm=146282&DocType=Customer+Drawing&DocLang=English
J22 J23 = CONN_RCPT_0: CONN RCPT .100" 20POS DUAL GOLD; Distributor_Part_Number: SAM1196-10-ND; Mfr_Name: Samtec; Mfr_Part_Number: SSQ-110-03-G-D; TI_Part_No: TI-CON-SSQ-110-03-G-D; Datasheet: http://www.samtec.com/documents/webfiles/cpdf/SSQ-1XX-XX-XXX-X-XX-XXX-XX-X-MKT.pdf
R15 R19 R25 R26 R28 R29 R34-R36 R40 R41 R46 R52 R53 R56 = RESISTOR: RES 33.0 OHM 1/16W 1% 0402 SMD; Distributor_Part_Number: 311-33.0LRCT-ND; Mfr_Name: Yageo; Mfr_Part_Number: RC0402FR-0733RL; Tolerance: ±1%; Datasheet: http://www.yageo.com/documents/recent/PYu-RC0402_51_RoHS_L_6.pdf
U11 U12 = SN74LVC1T45: IC, BUS XCVR, 1-BIT, NON INVERTING, 3-STATE, 6-PIN, SOT-23; Distributor_Part_Number: TI-IC-SN74LVC1T45DCKR; Mfr_Name: TEXAS INSTRUMENTS INC; Mfr_Part_Number: SN74LVC1T45DCKR; TI_Part_No: TI-IC-SN74LVC1T45DCKR; Datasheet: http://focus.ti.com/lit/ds/symlink/sn74lvc1t45.pdf
C2 C3 C7-C9 C14 C15 = C: CAP CER 0.1UF 10V 10% X5R 0402; Distributor_Part_Number: 587-1227-1-ND; Mfr_Name: Taiyo Yuden; Mfr_Part_Number: LMK105BJ104KV-F; TI_Part_No: TI-CAP-LMK105BJ104KV-F; Tolerance: +/-10%; Datasheet: 587-1227-1-ND
C5 = CAP: CAP 33000PF 16V CERAMIC X7R 0402; Distributor_Part_Number: 1276-1555-1-ND; Mfr_Name: Samsung; Mfr_Part_Number: CL05B333KO5NFNC; TI_Part_No: TI-CAP-CL05B333KO5NFNC; Tolerance: 10%; Voltage_Rating: 16 VDC; Datasheet: http://www.samsungsem.com/servlet/FileDownload?type=spec&file=CL05B333KO5NFNC.pdf
C10 C12 = CAP: CAP CER 27PF 25V 5% NP0 0402; Distributor_Part_Number: 490-6176-1-ND; Mfr_Name: Murata Electronics North America; Mfr_Part_Number: GRM1555C1E270JA01D; Tolerance: ±5%; Voltage_Rating: 25V; Datasheet: http://www.murata.com/products/catalog/pdf/c02e.pdf
D2 D5 = LED: LED CHIPLED 570NM GREEN 0603 SMD; Colour: Green; Distributor_Part_Number: 475-1409-1-ND; Mfr_Name: OSRAM Opto Semiconductors Inc; Mfr_Part_Number: LG Q971-KN-1; Datasheet: http://catalog.osram-os.com/catalogue/catalogue.do;jsessionid=DE4D071D0D2758CC117C711BF848053E?act=downloadFile&favOid=0200000600005069000100b6
J1 = CONN_MICRO_USB_5P_6G: CONN USB MICRO B RECPT SMT R/A; Distributor_Part_Number: 609-4618-1-ND; Mfr_Name: FCI; Mfr_Part_Number: 10118194-0001LF; TI_Part_No: TI-CON-10118194-0001LF
L1 L2 = BEAD_FERRITE: FERRITE CHIP 80 OHM 600MA 0603 SMD; Current_Rating: 600mA; DC_Resistance: 0.1; Distributor_Part_Number: TI-IND-CIM10U800NC; Mfr_Name: Samsung; Mfr_Part_Number: CIM10U800NC; TI_Part_No: TI-FB-CIM10U800NC; Datasheet: http://www.samsungsem.co.kr:8080/servlet/DownloadServlet?dir=partnumber&num=&fileName=CIB%2CCIM10+Series6.pdf
R3 R4 R20 R125-R127 = RESISTOR_v2: RES 270 OHM 1/10W 5% 0603 SMD; Distributor_Part_Number: P270GCT-ND; Mfr_Name: Panasonic Electronic Components; Mfr_Part_Number: ERJ-3GEYJ271V; Tolerance: ±5%; Datasheet: http://industrial.panasonic.com/www-cgi/jvcr13pz.cgi?E+PZ+3+AOA0001+ERJ3GEYJ271V+7+WW
R6 R7 R11 R13 R14 R16 R22 R30 R33 R44 R45 R49 R50 R117 R119 R121 R123 R128 = RESISTOR_v2: RES 10K OHM 1/16W 5% 0402 SMD; Distributor_Part_Number: 311-10KJRCT-ND; Mfr_Name: Yageo; Mfr_Part_Number: RC0402JR-0710KL; TI_Part_No: TI-RES-RC0402JR-0710KL; Tolerance: 5%
R8 R9 = RESISTOR_v2: RES 28.0 OHM 1/16W 1% 0402 SMD; Distributor_Part_Number: 311-28.0LRCT-ND; Mfr_Name: Yageo; Mfr_Part_Number: RC0402FR-0728RL; Tolerance: ±1%; Datasheet: http://www.yageo.com/documents/recent/PYu-RC0402_51_RoHS_L_6.pdf
R10 = RESISTOR: RES 1.50K OHM 1/16W 1% 0402 SMD; Distributor_Part_Number: 311-1.50KLRCT-ND; Mfr_Name: Yageo; Mfr_Part_Number: RC0402FR-071K5L; Tolerance: ±1%; Datasheet: http://www.yageo.com/documents/recent/PYu-RC0402_51_RoHS_L_6.pdf
R12 = RESISTOR_v2: RES 2.2K OHM 1/10W 5% 0402 SMD; Distributor_Part_Number: ERJ-2GEJ222X; Mfr_Name: Panasonic; Mfr_Part_Number: ERJ-2GEJ222X; Part Number: ERJ-2GEJ222X; TI_Part_No: TI-RES-ERJ-2GEJ222X
R21 = RESISTOR: RES 470 OHM 1/16W 1% 0402 SMD; Distributor_Part_Number: 311-470LRCT-ND; Mfr_Name: Yageo; Mfr_Part_Number: RC0402FR-07470RL; Tolerance: ±1%; Datasheet: http://www.yageo.com/documents/recent/PYu-RC0402_51_RoHS_L_6.pdf
U1 = TPD2EUSB30: IC ESD SOLUTION 2CH SOT3; Distributor_Part_Number: 296-25509-1-ND; Mfr_Name: TI; Mfr_Part_Number: TPD2EUSB30DRTR; TI_Part_No: TI-ESD-TPD2EUSB30; Datasheet: http://www.ti.com/lit/ds/symlink/tpd2eusb30.pdf
U2 = EEPROM-93C46B_4: IC SRL EE 1K 64X16 2.5V 8MSOP; Distributor_Part_Number: TI-IC-93LC46B-I/MS; Mfr_Name: Microchip; TI_Part_No: TI-IC-93LC46B-I/MS
U4 U9 = SN74LVC125A: IC BUS BUFF TRI-ST QD 14TSSOP; Distributor_Part_Number: 296-1222-2-ND; Mfr_Name: TEXAS INSTRUMENTS INC; TI_Part_No: TI-IC-SN74LVC125APWR; Datasheet: http://www.ti.com/lit/gpn/sn74lvc125a
U5 = FT2232_LQFP_48P: IC, USB UART/FIFO, MPSSE, 12/48MHz, 48-PIN, LQFP; Distributor_Part_Number: TI-IC-FT2232D; ICA_MFR_NAME: FUTURE TECHNOLOGY DEVICES INTERNATIONAL LTD; ICA_PARTNUM: $$2285313$$FT2232D; Mfr_Name: FUTURE TECHNOLOGY DEVICES INTERNATIONAL LTD; TI_Part_No: TI-IC-FT2232D; Datasheet: http://www.ftdichip.com/Documents/DataSheets/DS_FT2232D.pdf
U7 = SN74LVC126A: IC BUS BUFF TRI-ST QD 14TSSOP; Distributor_Part_Number: 296-26579-5-ND; Mfr_Name: TEXAS INSTRUMENTS INC; TI_Part_No: TI-IC-SN74LVC126APWR; Datasheet: http://www.ti.com/lit/gpn/sn74lvc126a
Y1 = CRYSTAL: CRYSTAL 6MHZ 18PF THRU; Distributor_Part_Number: SER3409-ND; Frequency: 6.0 MHz; Mfr_Name: Epson; Mfr_Part_Number: CA-301 6.0000M-C:PBFREE
C1 C4 = CAP: CAP CER 10UF 10V 10% X5R 0805; Distributor: Digi-Key; Distributor PN: 490-1709-1-ND; Distributor_Name: Digi-Key; Distributor_Part_Number: 490-1709-2-ND; Manufacturer: Murata Electronics North America; Manufacturer PN: GRM21BR61A106KE19L; Mfr_Name: Murata; Mfr_Part_Number: GRM21BR61A106KE19L; TI_Part_No: TI-CAP-GRM21BR61A106KE19L; Tolerance: 10%; Voltage_Rating: 10V
C6 = CAP: CAP CER 15PF 50V 5% NP0 0402; Distributor: Digi-Key; Distributor PN: 490-5888-2-ND; Distributor_Name: Digi-Key; Distributor_Part_Number: 490-5888-1-ND; Manufacturer: Murata Electronics North America; Manufacturer PN: GRM1555C1H150JA01D; Mfr_Name: Murata Electronics North America; Mfr_Part_Number: GRM1555C1H150JA01D; TI_Part_No: TI-CAP-GRM1555C1H150JA01D; Tolerance: ±5%; Voltage_Rating: 50V; Datasheet: http://media.digikey.com/pdf/Data%20Sheets/Murata%20PDFs/GRM%20Series%20Data.pdf
C13 C16 = C: CAP CER 10UF 6.3V 20% X5R 0603; Distributor_Part_Number: 490-3896-2-ND; Mfr_Name: Murata Electronics North America; Mfr_Part_Number: GRM188R60J106ME47D; TI_Part_No: TI-RES-GRM188R60J106ME47D; Tolerance: 20%; Voltage_Rating: 6.3V
C23 C24 = CAP: CAP CER 100UF 6.3V 20% X5R 1206; Distributor_Part_Number: 445-6008-2-ND; Mfr_Name: TDK Corportation; Mfr_Part_Number: C3216X5R0J107M160AB; Tolerance: 20%; Voltage_Rating: 6.3V; Datasheet: http://www.tdk.com/pdf/TDKMLCCCapRange.pdf
C46 = CAP: CAP CER 0.033UF 10V 10% X5R 0402; Distributor_Part_Number: 490-5411-1-ND; Mfr_Name: Murata Electronics North America; Mfr_Part_Number: GRM155R61A333KA01D; Tolerance: ±10%; Voltage_Rating: 10V; Datasheet: http://media.digikey.com/pdf/Data%20Sheets/Murata%20PDFs/GRM%20Series%20Data.pdf
D1 D6 = LED: LED CHIPLED 587NM YLW 0603 SMD; Colour: Yellow; Distributor_Part_Number: 475-2558-1-ND; Mfr_Name: OSRAM Opto Semiconductors Inc; Mfr_Part_Number: LY Q976-P1S2-36; Datasheet: http://catalog.osram-os.com/jsp/download.jsp?name=LO_LS_LY_Q976.pdf&url=/media/_en/Graphics/00043804_0.pdf
D3 = DIODE: DIODE SCHOTTKY 40V 0.03A 0603; Distributor_Part_Number: CD0603-B00340TR-ND; Mfr_Name: Bourns Inc; TI_Part_No: TI-DIO-CD0603-B00340
D4 D7 = LED: LED CHIPLED 633NM RED 0603 SMD; Colour: Red; Distributor_Part_Number: 475-2512-1-ND; Mfr_Name: OSRAM Opto Semiconductors Inc; Mfr_Part_Number: LS Q976-NR-1; Datasheet: http://catalog.osram-os.com/jsp/download.jsp?name=LO_LS_LY_Q976.pdf&url=/media/_en/Graphics/00043804_0.pdf
J12 = HEADER_2: CONN HEADR BRKWAY .100 2POS STR; Distributor_Part_Number: 5-146285-2-ND; Mfr_Name: TE Connectivity; Mfr_Part_Number: 5-146285-2; TI_Part_No: TI-CON-5-146285-2; Datasheet: http://www.te.com/commerce/DocumentDelivery/DDEController?Action=srchrtrv&DocNm=146285&DocType=Customer+Drawing&DocLang=English
L3 = INDUCTOR: INDUCTOR POWER 10UH 1007; Current_Rating: 1.5A; Distributor_Part_Number: 587-2189-1-ND; Mfr_Name: Taiyo Yuden; Mfr_Part_Number: CB2518T100K; TI_Part_No: TI-IND-CB2518T100K
Q1 Q3-Q5 = MOSFET_I_EN_GSD: MOSFET N-CH 50V 200MA SOT-23; Distributor_Part_Number: BSS138LT3GOSCT-ND; Mfr_Name: On Semi; TI_Part_No: TI-MOS-BSS138LT3G; Datasheet: http://www.onsemi.com/pub_link/Collateral/BSS138LT1-D.PDF
Q2 = MOSFET_I_EP_GSD: MOSFET P-CH 20V 3.7A SOT23-3; Distributor_Part_Number: SI2323DS-T1-GE3CT-ND; Mfr_Name: Vishay; TI_Part_No: TI-MOSFET-SI2323DS-T1-GE3
R1 = RESISTOR_v2: RES 100 OHM 1/10W 5% 0402 SMD; Distributor: Digi-Key; Distributor PN: P100JTR-ND; Distributor_Name: Digi-Key; Distributor_Part_Number: P100JCT-ND; Manufacturer: Panasonic Electronic Components; Manufacturer PN: ERJ-2GEJ101X; Mfr_Name: Panasonic - ECG; Mfr_Part_Number: ERJ-2GEJ101X; TI_Part_No: TI-RES-ERJ-2GEJ101X
R5 R118 R120 R122 = RESISTOR_v2: RES 100K OHM 1/16W 5% 0402 SMD; Distributor_Part_Number: 311-100KJRCT-ND; Mfr_Name: Yageo; Mfr_Part_Number: RC0402JR-07100KL; Tolerance: 5%
R17 = RESISTOR_v2: RES 51K OHM 1/16W 1% 0402; Distributor: Digi-Key; Distributor PN: 1276-4178-2-ND; Distributor_Name: Digi-Key; Distributor_Part_Number: 1276-4178-1-ND; Manufacturer: Samsung Electro-Mechanics America, Inc; Manufacturer PN: RC1005F513CS; Mfr_Name: Samsung; Mfr_Part_Number: RC1005F513CS; TI_Part_No: TI-RES-RC1005F513CS; Tolerance: 1%
R18 = RESISTOR_v2: RES 30.1K OHM 1/16W 1% 0402 SMD; Distributor: Digi-Key; Distributor PN: 311-30.1KLRTR-ND; Distributor_Name: Digi-Key; Distributor_Part_Number: 311-30.1KLRCT-ND; Manufacturer: Yageo; Manufacturer PN: RC0402FR-0730K1L; Mfr_Name: Yageo; Mfr_Part_Number: RC0402FR-0730K1L; TI_Part_No: TI-RES-RC0402FR-0730K1L; Tolerance: 1%
R23 R27 R32 R38 R39 R42 R43 R48 R51 R55 R115 = RESISTOR_v2: RES 0.0 OHM 1/10W JUMP 0402 SMD; Distributor_Part_Number: P0.0JTR-ND; Mfr_Name: Panasonic Electronic Components; Mfr_Part_Number: ERJ-2GE0R00X; TI_Part_No: TI-Panasonic-ERJ-2GE0R00X
R37 R112 = RESISTOR_v2: DO NOT MOUNT; Distributor_Part_Number: TI-RES-DNP-0603; Tolerance: NA
R47 R54 = RESISTOR_v2: RES 3.3K OHM 1/10W 5% 0402 SMD; Distributor_Part_Number: P3.3KJCT-ND; Mfr_Name: Panasonic - ECG; Mfr_Part_Number: ERJ-2GEJ332X; TI_Part_No: TI-RES-ERJ-2GEJ332X; Tolerance: 5%; Datasheet: http://industrial.panasonic.com/www-cgi/jvcr13pz.cgi?E+PZ+3+AOA0001+ERJ2GEJ332X+7+WW
R100 = RESISTOR_v2: RES 3.30M OHM 1/16W 1% 0402 SMD; Distributor_Part_Number: 311-3.30MLRCT-ND; Mfr_Name: Yageo; Mfr_Part_Number: RC0402FR-073M3L; Tolerance: ±1%; Datasheet: http://www.yageo.com/documents/recent/PYu-RC0402_51_RoHS_L_6.pdf
R116 R124 = RESISTOR_v2: RES 1.0K OHM 1/16W 5% 0402 SMD; Distributor_Part_Number: 311-1.0KJRCT-ND; Mfr_Name: Yageo; Mfr_Part_Number: RC0402JR-071KL; Tolerance: 5%
SW1-SW3 = SW_TACT_SPST: SWITCH TACTILE SPST-NO 0.02A 15V; Distributor_Part_Number: P8070SCT-ND; Mfr_Name: Panasonic; Mfr_Part_Number: EVQ-11A04M; Datasheet: http://industrial.panasonic.com/www-data/pdf/ATK0000/ATK0000CE11.pdf
TP1 = TP_1206: 1206 PROBE PAD; Distributor: Digi-Key; Distributor PN: A106146CT-ND; Distributor_Name: Digi-Key; Distributor_Part_Number: A106146CT-ND; Manufacturer: TE Connectivity; Manufacturer PN: 1625854-4; Mfr_Name: TE Connectivity; Mfr_Part_Number: 1625854-4; TI_Part_No: TI-TP-1625854-4
U3 = TPS79601_SOT-223_0: IC,VREG,LDO,1.2V-5.5V,2.7V-5.5V,--,6PIN,SOT-223; Distributor: Digikey; Distributor PN: 296-13761-2-ND; Distributor_Name: Digikey; Distributor_Part_Number: 296-13761-2-ND; Manufacturer: TEXAS INSTRUMENTS INC; Manufacturer PN: TPS79601DCQR; Mfr_Name: TEXAS INSTRUMENTS INC; Mfr_Part_Number: TPS79601DCQR; TI_Part_No: TI_TPS79601DCQR
U6 = TMP006: IC SENSOR THERMOPILE 8DSBGA; Distributor_Part_Number: 296-28819-1-ND; Mfr_Name: Texas Instruments; Mfr_Part_Number: TMP006AIYZFR; TI_Part_No: TI-SENSOR-TMP006AIYZFR; Datasheet: http://www.ti.com/lit/ds/symlink/tmp006.pdf
U8 = TPS61097-33: IC REG BST SYNC 3.3V .1A SOT23-5; Distributor_Part_Number: 296-24662-2-ND; Mfr_Name: TEXAS INSTRUMENTS INC; TI_Part_No: TI-IC-TPS61097-33DBVR; Datasheet: http://www.ti.com/lit/ds/symlink/tps61097-33.pdf
U10 = BMA222: 3-AXIS ACCELEROMETER DIGITAL SMD; Distributor_Part_Number: 828-1039-1-ND; Mfr_Name: Bosch; Mfr_Part_Number: BMA222E; TI_Part_No: TI-SENSOR-BMA222E; Datasheet: http://ae-bst.resource.bosch.com/media/products/dokumente/bma222e/BST-BMA222E-DS004-03_published.pdf

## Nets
GND: C1.2 C2.2 C3.2 C4.2 C5.2 C7.2 C8.2 C9.2 C10.2 C11.2 C12.2 C13.2 C14.2 C15.2 C16.2 C17.2 C18.2 C19.2 C20.2 C21.2 C22.2 C23.2 C24.2 C25.2 C26.2 C27.2 C28.2 C29.2 C30.2 C31.2 C32.2 C33.2 C34.2 C35.2 C36.2 C37.2 C38.2 C39.2 C40.2 C41.2 C42.2 C43.2 C44.2 C45.2 C46.2 C47.2 C48.2 C50.1 C50.2 D4.2(CATHODE) E1.1(Feed) E1.2 FL1.2(GND1) FL1.4(GND2) J1.G1 J1.G2 J1.G3 J1.G4 J1.G5 J1.G6 J5.5 J18.2A(GND1) J18.2B(GND2) J19.2 J19.3 J20.2 J20.3 J22.4 J23.2 J24.3(GND1) J24.4(GND2) L1.1(Z1) L8.1 L9.2 Q1.2(S) Q3.2(S) Q4.2(S) Q5.2(S) R1.1 R11.2 R18.1 R23.1 R31.1 R33.2 R45.2 R49.2 R50.2 R51.1 R58.2 R59.2 R61.2 R100.2 R115.1 R117.2 R118.2 R120.2 R122.2 R128.2 TP1.1 U1.3(GND) U2.5(GND) U3.3(GND) U3.6(TAB) U4.7(GND) U5.9(GND) U5.18(GND) U5.25(GND) U5.34(GND) U5.45(AGND) U5.47(TEST) U6.A1(DGND) U6.A2(AGND) U7.7(GND) U8.2(GND) U9.7(GND) U10.8(GNDIO) U10.9(GND) U11.2(GND) U11.5(DIR) U12.2(GND) U13.65(GND_TAB) U14.4(GND) U14.9(TAB) U15.4(GND) Y3.2 Y3.4
VBAT_CC: C23.1 C24.1 C29.1 C33.1 C35.1 C38.1 C39.1 C40.1 J12.1 R62.2 U13.10(VIN_IO1) U13.37(VIN_DCDC_ANA) U13.39(VIN_DCDC_PA) U13.44(VIN_DCDC_DIG) U13.54(VIN_IO2) U14.3(~{WP}) U14.7(~{RESET}) U14.8(VCC) U15.3(~{WP}) U15.7(~{RESET}) U15.8(VCC)
VBUS_USB1: C1.1 L2.2(Z2) R2.1 R21.2(B) U3.1(EN) U3.2(IN) U5.3(VCC) U5.4(RESET#) U5.42(VCC)
VCC_BRD: C13.1 C19.1 C22.1 D1.1(ANODE) D5.1(ANODE) D6.1(ANODE) D7.1(ANODE) J12.2 J13.1 J22.1 L3.1 Q2.2(S) R5.1 R20.1 R24.2 R27.2 R32.2 R43.2 R47.1 R54.1 R57.1 R62.1 R112.2 R116.1 R124.1 U8.1(VIN) U8.3(EN) U11.1(VCCA) U12.1(VCCA) U12.5(DIR)
VCC_DCDC_3V3: C16.1 R64.2 U8.4(OUT)
VCC_LDO_3V3: C2.1 C3.1 C4.1 C6.1 C7.1 C9.1 C14.1 C15.1 C18.1 C20.1 D2.1(ANODE) J13.2 R6.1 R7.1 R13.1 R14.1 R16.1 R17.2 R22.1 R30.1 R44.1 U2.8(Vcc) U3.4(OUT) U4.14(Vcc) U5.14(VCCIOA) U5.31(VCCIOB) U7.4(EN) U7.14(Vcc) U9.1(*) U9.14(Vcc) U11.6(VCCB) U12.6(VCCB)
VCC_MCU_5V: J19.1 J22.2 R2.2
VDD_ANA: C31.1 C41.1 C43.1 C45.1 L7.1 U13.25(LDO_IN2) U13.36(LDO_IN1) U13.48(VDD_ANA1)
VDD_DIG_CC: C28.1 C32.1 C37.1 L5.1 U13.9(VDD_DIG1) U13.56(VDD_DIG2)
VDD_PA: C34.1 C36.1 C42.1 U13.33(VDD_PA_IN) U13.42(DCDC_PA_OUT)
VDD_PLL: C44.1 U13.24(VDD_PLL)
VDD_RAM: C30.1 U13.49(VDD_RAM)
BRD_JTAG_TCK: J8.1 R15.2(B)
BRD_JTAG_TDI: J10.1 R19.2(B)
BRD_JTAG_TDO: J11.1 R25.2(B)
BRD_JTAG_TMS: J9.1 R29.2(B)
CC_GPIO_00: R77.1 R107.2 U13.50(GPIO_00)
CC_GPIO_01: J7.2 U13.55(GPIO_01)
CC_GPIO_02: J6.2 U13.57(GPIO_02)
CC_GPIO_03: R67.1 R76.2 U13.58(GPIO_03)
CC_GPIO_04: R87.1 R94.2 U13.59(GPIO_04)
CC_GPIO_05: J5.2 R72.2 R97.1 U13.60(GPIO_05)
CC_GPIO_06: R82.1 R85.1 U13.61(GPIO_06)
CC_GPIO_07: J5.1 R81.1 R92.1 R96.1 U13.62(GPIO_07)
CC_GPIO_08: R95.2 U13.63(GPIO_08)
CC_GPIO_09: R79.1 R103.2 R122.1 R123.1 U13.64(GPIO_09)
CC_GPIO_10: J3.2 R71.1 R102.1 R120.1 R121.1 U13.1(GPIO_10)
CC_GPIO_11: J2.2 R63.1 R106.1 R118.1 R119.1 U13.2(GPIO_11)
CC_GPIO_12: R78.1 U13.3(GPIO_12)
CC_GPIO_13: J4.1 R37.2 R73.1 R117.1 SW3.1 U13.4(GPIO_13)
CC_GPIO_14: R91.1 U13.5(GPIO_14)
CC_GPIO_15: R86.2 R93.2 U13.6(GPIO_15)
CC_GPIO_16: R89.2 R90.2 U13.7(GPIO_16)
CC_GPIO_17: R75.2 U13.8(GPIO_17)
CC_GPIO_22: R109.2 R128.1 SW2.1 U13.15(GPIO_22)
CC_GPIO_23: J10.2 R104.1 U13.16(GPIO_23/JTAG_TDI)
CC_GPIO_24: J11.2 R74.1 R108.1 U13.17(GPIO_24/JTAG_TDO)
CC_GPIO_26: J5.3 R66.1 U13.29(ANTSEL1)
CC_GPIO_27: J5.4 R68.1 U13.30(ANTSEL2)
CC_GPIO_28: R69.2 R88.1 U13.18(GPIO_28)
CC_GPIO_30: R99.2 U13.53(GPIO_30)
CC_GPIO_31: R65.2 R80.2
CC_nRESET: C46.1 D3.2(K) Q1.1(G) R5.2 R100.1 R129.2 SW1.2 U13.32(nRESET)
DBG_RST_n: R30.2 U5.19(ADBUS5) U9.10(*)
DBGENn: R4.2 R22.2 R28.2(B) U4.1(*) U4.4(*) U4.10(*) U4.13(*)
DBGMOD: R26.2(B) U4.2(A) U4.5(A)
FT_CS: R34.2(B) U7.9(A) U9.5(A)
FT_DI: R36.2(B) U7.11(Y) U9.11(Y)
FT_DO: R41.2(B) U4.9(A) U7.2(A)
FT_SK: R46.2(B) U4.12(A)
FTDI_RX: R40.2(B) R53.2(B)
FTDI_TX: R35.2(B) U11.4(B)
LP_GPIO_01: J7.1 R105.2
LP_GPIO_02: J6.1 R70.2
LP_GPIO_25: J14.1 R83.1 R98.2
LP_RESET_OUT: D3.1(A) R84.2
PA_SWN: L6.1 U13.41(DCDC_PA_SW_N)
PA_SWP: L6.2 U13.40(DCDC_PA_SW_P)
SENS_I2C_SCL: J3.1 R39.1 R47.2 R48.1
SENS_I2C_SDA: J2.1 R38.1 R54.2 R55.1
SFL_CLK: U13.11(FLASH_SPI_CLK) U14.6(CLK) U15.6(CLK)
SFL_CS: U13.14(FLASH_SPI_CS#) U14.1(~{CS}) U15.1(~{CS})
SFL_DIN: U13.13(FLASH_SPI_DIN) U14.2(DOUT) U15.2(DOUT)
SFL_DOUT: U13.12(FLASH_SPI_DOUT) U14.5(DIN) U15.5(DIN)
SOP0: J17.1 R59.1 U13.35(SOP0)
SOP1: J16.1 R58.1 U13.34(SOP1)
SOP2: J15.1 R60.1 R61.1
SRSTn: R52.2(B) R129.1
N24159: L7.2 U13.38(DCDC_ANA_SW)
N24403: L5.2 U13.43(DCDC_DIG_SW)
N24535: L4.2 R65.1 U13.45(DCDC_ANA2_SW_P)
N24539: L4.1 U13.46(DCDC_ANA2_SW_N)
N24551: C27.1 R64.1 U13.47(VDD_ANA2)
N27756: FL1.1(IN) U13.31(RF_BG)
N28553: C25.1 U13.51(RTC_XTAL_P) Y2.1
N28565: C26.1 U13.52(RTC_XTAL_N) Y2.2
N30169: C47.1 U13.22(WLAN_XTALM) Y3.3
N36298: J9.2 U13.20(GPIO_29/JTAG_TMS)
N36324: J8.2 U13.19(GPIO_28/JTAG_TCK)
N49988: J15.2 J16.2 J17.2 R57.2
N54209: J22.3 R67.2
N54213: J22.19 R106.2
N54217: J22.5 R73.2
N54221: J22.7 R78.2
N54244: J22.15 R96.2
N54248: J22.17 R102.2
N141545: C48.1 R101.2 Y3.1
N178690: J14.2 R60.2 U13.21(GPIO_25/SOP2)
N185612: C17.1 C21.1 R42.1 R43.1 U10.3(VDDIO) U10.7(VDD)
N185801: C11.1 R27.1 U6.A3(Vcc)
N186121: R51.2 U10.1(SDO/ADD0)
N186159: R42.2 U10.11(PS)
N186206: R48.2 U10.12(SCx)
N186210: R55.2 U10.2(SDx)
N187169: R31.2 R32.1 U6.C1(ADDR0)
N187173: R23.2 R24.1 U6.B1(ADDR1)
N187525: R39.2 U6.B3(SCL)
N187543: R38.2 U6.C3(SDA)
N187584: R37.1 U6.C2(\~{DTRDY})
N187626: J4.2 U10.5(INT1)
N192685: J22.11 R87.2
N195183: D4.1(ANODE) R20.2
N195451: C6.2 R17.1 R18.2 U3.5(FB)
N197053: R101.1 U13.23(WLAN_XTALP)
N224301: C49.1 R110.2
N224305: C49.2 J18.1(CENTER) L8.2
N224377: FL1.3(OUT) R110.1 R111.1
N224405: J24.1(IN) R111.2
N233208: J22.18 R103.1
N288081: J23.16 R98.1
N288085: J23.14 R90.1 R93.1
N288162: J23.4 R69.1
N288174: J23.10 R84.1
N288178: J23.12 R86.1 R89.1
N288672: J23.3 R68.2 R71.2
N288674: J23.5 R74.2
N288676: J23.7 R77.2 R79.2 R81.2
N288678: J23.9 R83.2 R85.2
N288680: J23.11 R88.2
N288682: J23.13 R92.2
N288684: J23.15 R97.2
N288686: J23.17 R104.2
N288688: J23.19 R108.2
N288796: J23.1 R63.2 R66.2
N292143: J20.1 Q2.3(D) R112.1
N314690: J6.3 R56.1(A)
N329065: Q2.1(G) R115.2
N394921: L3.2 U8.5(L)
N412421: J22.6 R70.1
N412425: J22.8 R72.1
N439074: J23.20 R109.1
N439968: J22.20 R107.1
N454667: J23.8 R80.1
N454954: J22.10 R76.1
N454967: J22.12 R94.1
N466203: J22.9 R82.2
N466207: J22.13 R91.2
N466247: J22.14 R95.1
N466251: J22.16 R99.1
N466300: J23.6 R75.1
N466314: J23.18 R105.1
N474715: J24.2(OUT) L9.1
N487558: R9.2 R10.1(A) U5.7(USBDP)
N487570: C5.1 U5.6(3V3OUT)
N487672: C8.1 R21.1(A) U5.46(AVCC)
N487804: R10.2(B) U5.5(RSTOUT#)
N487824: R44.2 U5.26(SI/WUB)
N487832: R7.2 U5.10(SI/WUA)
N487932: R40.1(A) U5.39(BDBUS1)
N488104: R35.1(A) U5.40(BDBUS0)
N488180: R14.2 U2.2(CLK) U5.1(EESK)
N488188: R13.2 U2.1(CS) U5.48(EECS)
N488454: R46.1(A) U5.24(ADBUS0)
N488458: R41.1(A) U5.23(ADBUS1)
N488478: R6.2 R12.1 U2.4(DOUT)
N488614: R12.2 U2.3(DIN) U5.2(EEDATA)
N488706: C10.1 U5.44(XTOUT) Y1.1
N488714: C12.1 U5.43(XTIN) Y1.2
N489641: R36.1(A) U5.22(ADBUS2)
N489651: R34.1(A) U5.21(ADBUS3)
N490588: J1.1(Vcc) L2.1(Z1)
N490592: J1.5(GND) L1.2(Z2)
N490656: J1.2(D-) R8.1 U1.2(D-)
N490660: J1.3(D+) R9.1 U1.1(D+)
N497403: R8.2 U5.8(USBDM)
N507782: R28.1(A) U5.17(ADBUS6)
N507786: R26.1(A) U5.16(ADBUS7)
N508362: R16.2 U4.6(Y) U9.4(*) U9.13(*)
N508615: R11.1 U4.3(Y) U7.10(EN) U7.13(EN)
N509670: R15.1(A) U4.11(Y)
N509674: R19.1(A) U4.8(Y)
N511498: R49.1 U7.1(EN) U9.6(Y)
N512182: R29.1(A) U7.3(Y) U7.8(Y) U9.12(A)
N512199: R25.1(A) U7.12(A)
N517852: R50.1 U9.9(A)
N517913: D2.2(CATHODE) R4.1
N518669: R52.1(A) U9.8(Y)
N519131: R33.1 U7.5(A)
N519138: R45.1 U9.2(A)
N532592: J7.3 U12.3(A)
N532639: R53.1(A) U12.4(B)
N533262: R56.2(B) U11.3(A)
N553084: R124.2 SW2.2
N553120: R116.2 SW3.2
N553666: R1.2 SW1.1
N555301: D1.2(CATHODE) R3.1
N555325: Q1.3(D) R3.2
N555403: D7.2(CATHODE) R127.1
N555427: D5.2(CATHODE) R125.1
N555431: D6.2(CATHODE) R126.1
N555483: Q5.3(D) R127.2
N555487: Q4.3(D) R126.2
N555495: Q3.3(D) R125.2
N555589: Q3.1(G) R119.2
N555601: Q4.1(G) R121.2
N555605: Q5.1(G) R123.2

Not connected (* = marked no-connect by the designer): J1 4(ID)*; U2 6(NC2)* 7(NC1)*; U5 11(ACBUS3) 12(ACBUS2) 13(ACBUS1) 15(ACBUS0) 20(ADBUS4) 27(BCBUS3) 28(BCBUS2) 29(BCBUS1) 30(BCBUS0) 32(BDBUS7) 33(BDBUS6) 35(BDBUS5) 36(BDBUS4) 37(BDBUS3) 38(BDBUS2) 41(PWREN#); U7 6(Y); U9 3(Y); U10 4(NC) 6(INT2) 10(CSB); U13 26(NC) 27(NC) 28(NC)

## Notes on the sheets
sheet 1
- TEMP SENSOR
- ACCELEROMETER
- Isolate sensor I2C
- SWITCHES & RESET
- LED INDICATORS
- Reset from Emulator
- POWER MANAGEMENT
- Measure the
  CC3200 Current
- 1A LDO
- DC/DC for Flash
- (BOOST MODE ONLY)
- BATT CONN
  (2xAA ONLY)
- Reverse voltage
  protection
sheet 2
- EMULATION CIRCUIT
- JTAG/SWD SWITCH
sheet 3
- BOOSTER PACK INTERFACE
- For Antenna diversity
- P4
- P2
- P1
- P3
- PWR
- P1.1
- P3.1
- PWR
- PWM/GPIO
- PWM/GPIO
- P4.1
- P4.2
- P2.1
- P2.2
- GPIO
- ANA IN
- P1.2
- P3.2
- GND
- PWM/GPIO
- P4.3
- P2.3
- SPI_CS
- RX
- P1.3
- P3.3
- ANA IN
- PWM/GPIO
- P4.4
- P2.4
- TEST
- TX
- P1.4
- P3.4
- ANA IN
- CCP/GPIO
- P4.5
- P2.5
- RESET
- GPIO
- P1.5
- P3.5
- CCP/GPIO
- P4.6
- P2.6
- SPI_MOSI
- ANA IN
- SPI CLK
- P1.6
- P1.7
- P3.6
- P3.7
- I2S FSYNC
- GPIO/NWP_LOG
- GPIO/WLAN_LOG
- P4.7
- P4.8
- P2.7
- P2.8
- GPIO
- SPI_MISO
- GPIO
- P1.8
- P3.8
- I2S CLK
- GPIO/RS232_RX
- P4.9
- P2.9
- GPIO
- SCL
- P1.9
- P3.9
- I2S DOUT
- GPIO/RS232_TX
- P4.10
- P2.10
- GPIO
- SDA
- P1.10
- P3.10
- I2S DIN
- Alternate RTS
- Alternate CTS
- SWAP MOSI/MISO
- UART MUXING
- TEST POINTS
- OBSERVE NWP & MAC LOG
- LEVEL SHIFTER
- FLASH PROGRAMMING
- Set 2-3 for flashing
- Set 1-2 to route to BP Conn
- LEVEL SHIFTER
sheet 4
- 50 Ohm
- 50 Ohm
- 50 Ohm
- CHIP ANTENNA
- 50 Ohm
- 50 Ohm
- ONLY ONE FLASH USED ON BOARD
- TO FTDI
